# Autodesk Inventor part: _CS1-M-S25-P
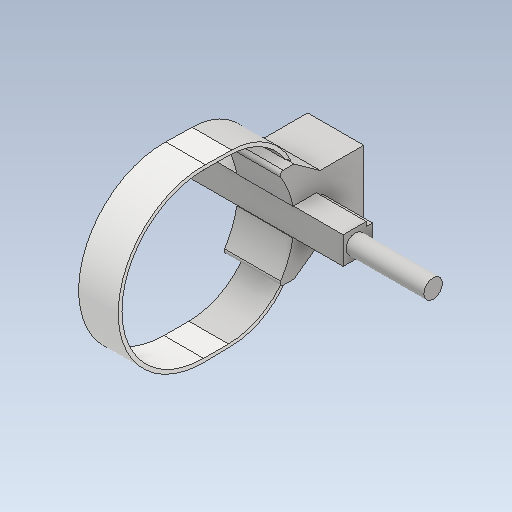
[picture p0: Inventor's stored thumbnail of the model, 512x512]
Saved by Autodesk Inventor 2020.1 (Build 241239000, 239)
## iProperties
Created: 2020-04
Part Number: _CS1-M-S25-P
Material: Generic
Document SubType Name: Modeling
Designer: Safarabadi
Density: 1 g/cm^3
Appearance: Default
Author: Safarabadi
Revision Number: NONE
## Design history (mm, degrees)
feature "_CS1-M-S25-P"
body "Solid1"
